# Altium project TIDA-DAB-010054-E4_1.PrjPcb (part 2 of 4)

## Sheet TIDA-DAB-010054-E4_SecondarySideSensing.SchDoc
size 431 x 279 mm; Date: Not shown in title block; ApprovedBy: Not shown in title block; CheckedBy: Not shown in title block; Author: Not shown in title block; CompanyName: Not shown in title block; Engineer: Not shown in title block; Organization: Not shown in title block; Address1: Not shown in title block; Address2: Not shown in title block; Address3: Not shown in title block; Address4: Not shown in title block; DocumentNumber: 1; Revision: Use project parameter SCH_Rev; SheetNumber: 4; SheetTotal: 11; PageSetup: Record=PageOptions¦CenterHorizontal=True¦CenterVertical=True¦PrintScale=1.00¦XCorrection=1.00¦YCorrection=1.00¦PrintKind=0¦BorderSize=5000000¦LeftOffset=0¦BottomOffset=0¦Orientation=2¦PaperLength=1000¦PaperWidth=1000¦Scale=100¦PaperSource=15¦PrintQuality=600¦MediaType=1¦DitherType=10¦PaperKind=Letter¦PrintScaleMode=1
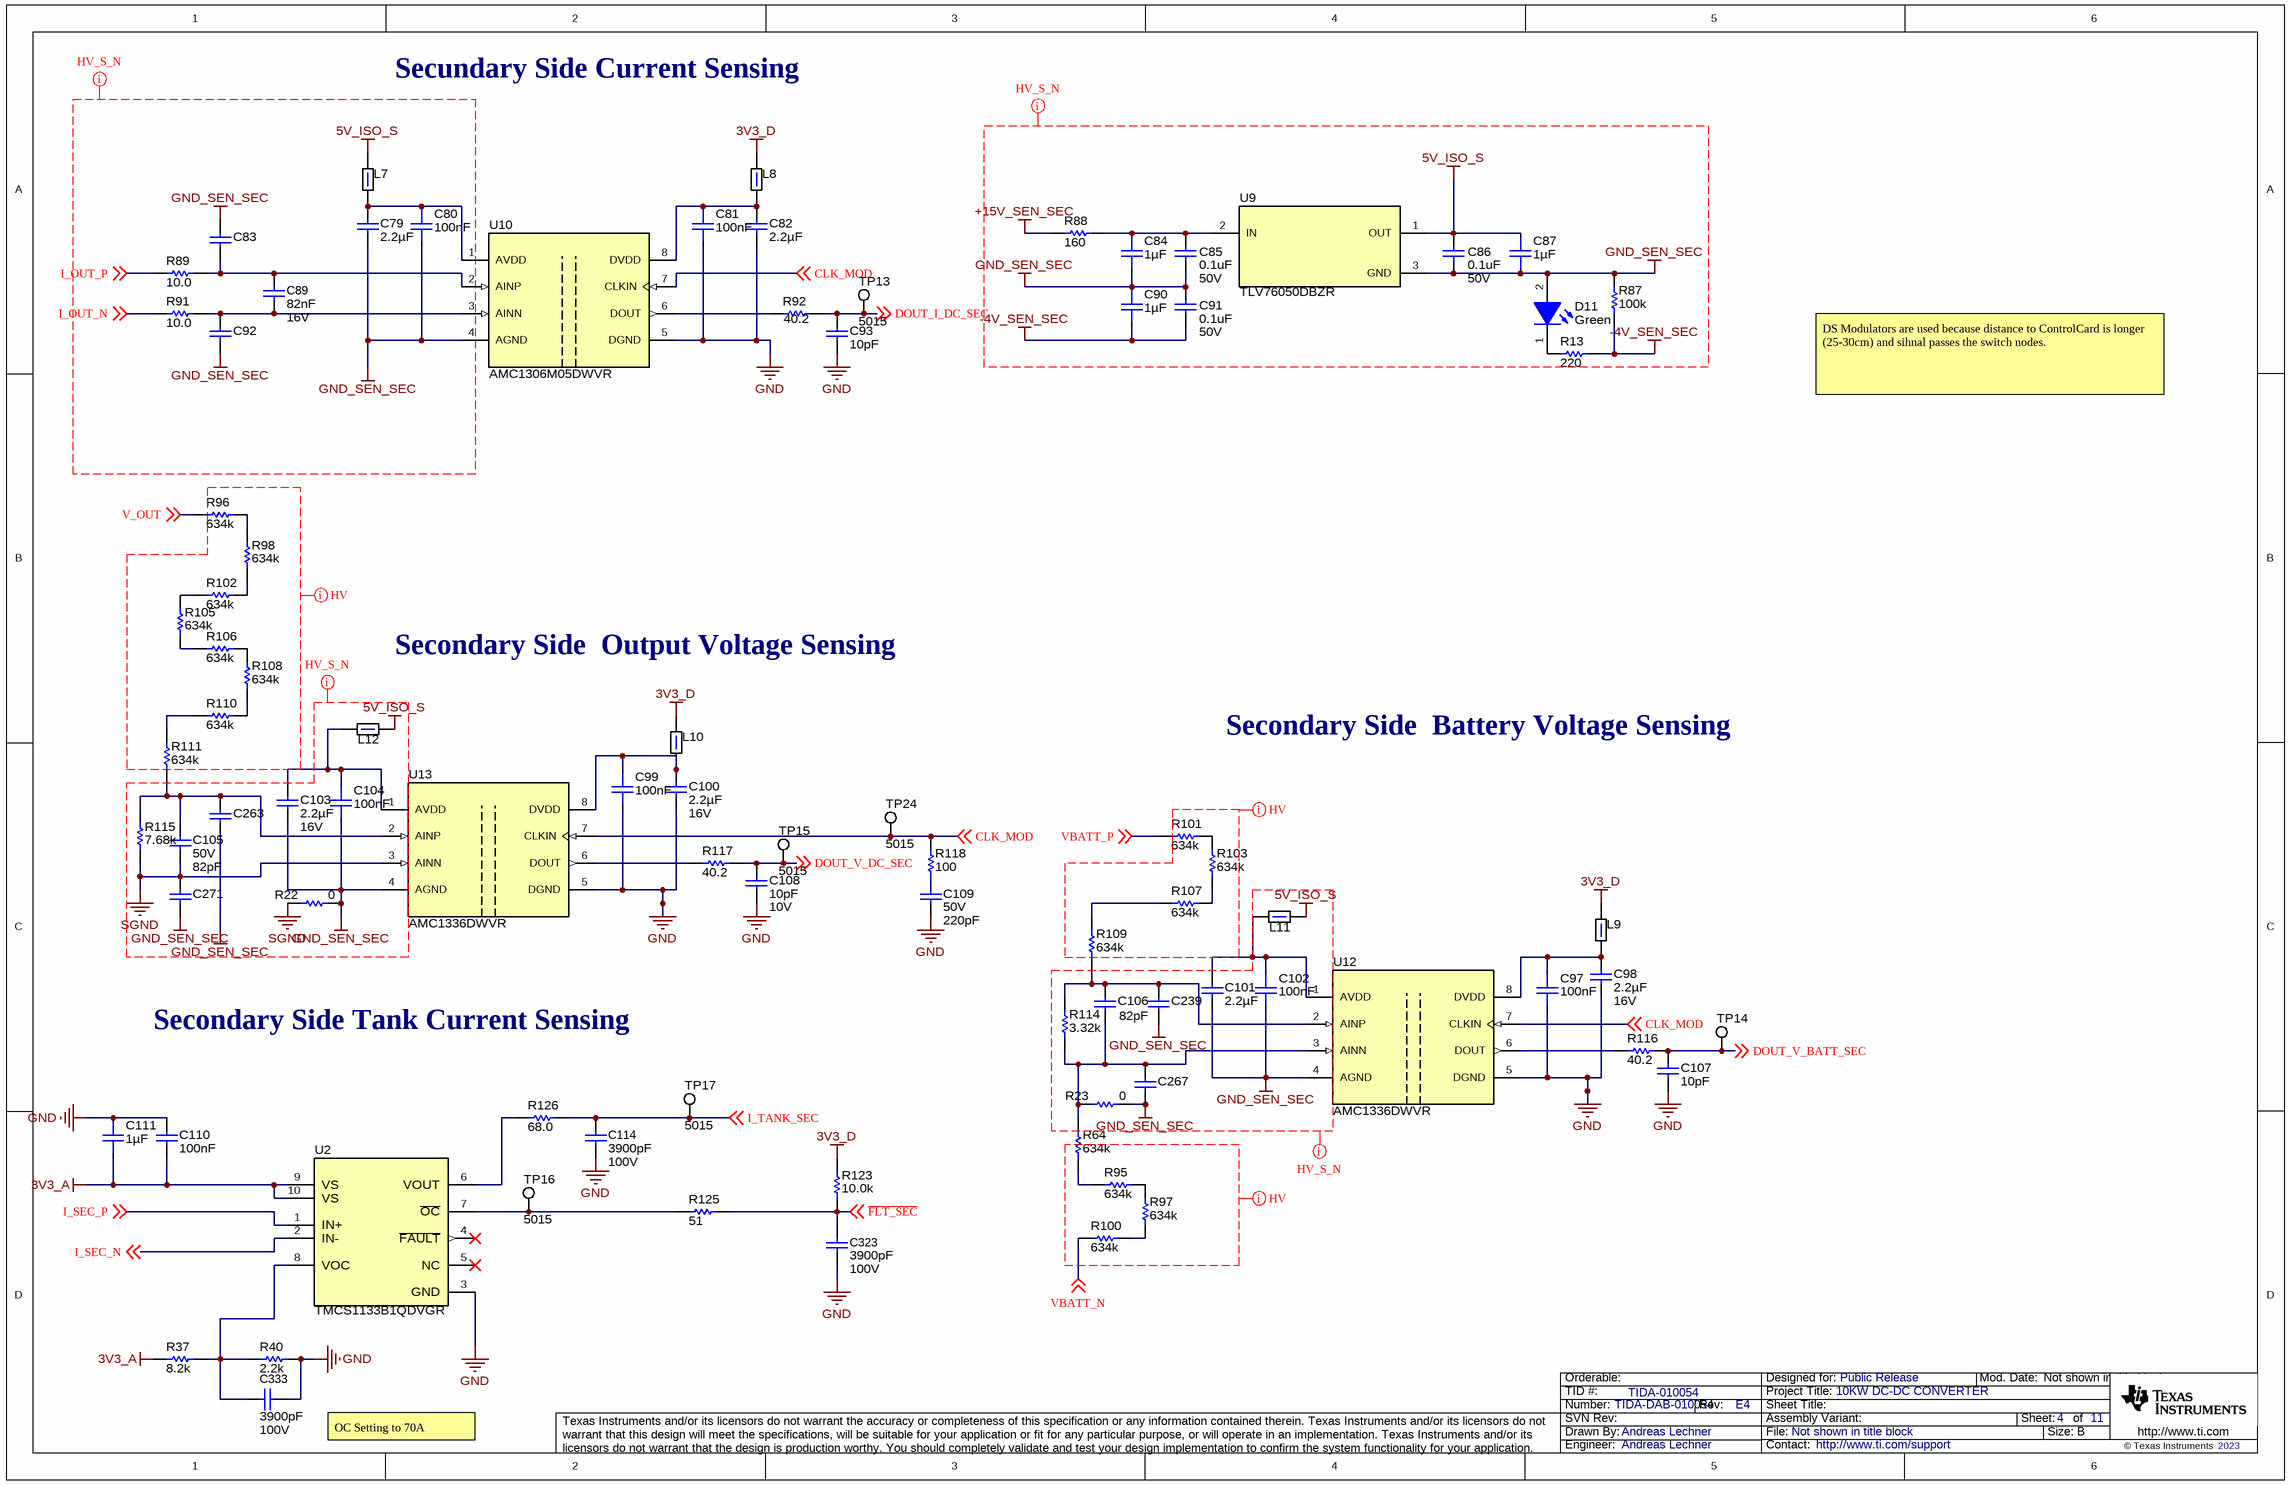
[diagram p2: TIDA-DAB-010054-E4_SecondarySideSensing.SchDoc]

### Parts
C79  Cap_F: 2.2µF  [0603]  (hidden comment: CC0603KRX7R7BB225)
C80  Cap_F: 100nF  [FP-CL10B104KA8VPJC_0603-MFG]  (hidden comment: CL10B104KA8VPJC)
C81  Cap_F: 100nF  [FP-CL10B104KA8VPJC_0603-MFG]  (hidden comment: CL10B104KA8VPJC)
C82  Cap_F: 2.2µF  [0603]  (hidden comment: CC0603KRX7R7BB225)
C83  0603ZC100KAT2A  [0603]  (value not drawn)
C84  Cap_F: 1µF  [FP-CL10B105KA8VPJC_0603-MFG]  (hidden comment: CL10B105KA8VPJC)
C85  VDC_V: 50V  ValueDisplayed: 0.1uF  [0402L]  (hidden comment: GCM155R71H104KE02D)
C86  VDC_V: 50V  ValueDisplayed: 0.1uF  [0402L]  (hidden comment: GCM155R71H104KE02D)
C87  Cap_F: 1µF  [FP-CL10B105KA8VPJC_0603-MFG]  (hidden comment: CL10B105KA8VPJC)
C89  Cap_F: 82nF  VDC_V: 16V  [0603]  (hidden comment: 0603YC823KAT2A)
C90  Cap_F: 1µF  [FP-CL10B105KA8VPJC_0603-MFG]  (hidden comment: CL10B105KA8VPJC)
C91  VDC_V: 50V  ValueDisplayed: 0.1uF  [0402L]  (hidden comment: GCM155R71H104KE02D)
C92  0603ZC100KAT2A  [0603]  (value not drawn)
C93  Cap_F: 10pF  [0603]  (hidden comment: 0603ZC100KAT2A)
C97  Cap_F: 100nF  [FP-CL10B104KA8VPJC_0603-MFG]  (hidden comment: CL10B104KA8VPJC)
C98  Cap_F: 2.2µF  VDC_V: 16V  [0603]  (hidden comment: CC0603KRX7R7BB225)
C99  Cap_F: 100nF  [FP-CL10B104KA8VPJC_0603-MFG]  (hidden comment: CL10B104KA8VPJC)
C100  Cap_F: 2.2µF  VDC_V: 16V  [0603]  (hidden comment: CC0603KRX7R7BB225)
C101  Cap_F: 2.2µF  [0603]  (hidden comment: CC0603KRX7R7BB225)
C102  Cap_F: 100nF  [FP-CL10B104KA8VPJC_0603-MFG]  (hidden comment: CL10B104KA8VPJC)
C103  Cap_F: 2.2µF  VDC_V: 16V  [0603]  (hidden comment: CC0603KRX7R7BB225)
C104  Cap_F: 100nF  [FP-CL10B104KA8VPJC_0603-MFG]  (hidden comment: CL10B104KA8VPJC)
C105  VDC_V: 50V  ValueDisplayed: 82pF  [0603]  (hidden comment: C0603C820K5GACTU)
C106  ValueDisplayed: 82pF  [0603]  (hidden comment: C0603C820K5GACTU)
C107  Cap_F: 10pF  [0603]  (hidden comment: 0603ZC100KAT2A)
C108  Cap_F: 10pF  VDC_V: 10V  [0603]  (hidden comment: 0603ZC100KAT2A)
C109  VDC_V: 50V  ValueDisplayed: 220pF  [0603]  (hidden comment: GRM1885C1H221JA01D)
C110  Cap_F: 100nF  [0603]  (hidden comment: 06033C104KAT2A)
C111  Cap_F: 1µF  [FP-CL10B105KA8VPJC_0603-MFG]  (hidden comment: CL10B105KA8VPJC)
C114  ValueDisplayed: 3900pF  VDC_V: 100V  [0603]  (hidden comment: C1608C0G2A392J080AE)
C239  0603ZC100KAT2A  [0603]  (value not drawn)
C263  0603ZC100KAT2A  [0603]  (value not drawn)
C267  0603ZC100KAT2A  [0603]  (value not drawn)
C271  0603ZC100KAT2A  [0603]  (value not drawn)
C323  ValueDisplayed: 3900pF  VDC_V: 100V  [0603]  (hidden comment: C1608C0G2A392J080AE)
C333  ValueDisplayed: 3900pF  VDC_V: 100V  [0603]  (hidden comment: C1608C0G2A392J080AE)
D11  value Green  [WL-SMCW_GREEN]  (hidden comment: 150060VS75000)
L7  74279228260  [0603]  (value not drawn)
L8  74279228260  [0603]  (value not drawn)
L9  74279228260  [0603]  (value not drawn)
L10  74279228260  [0603]  (value not drawn)
L11  74279228260  [0603]  (value not drawn)
L12  74279228260  [0603]  (value not drawn)
R13  ValueDisplayed: 220  [0603]  (hidden comment: CRCW0603220RJNEA)
R22  ValueDisplayed: 0  [0603]  (hidden comment: RMCF0603ZT0R00)
R23  ValueDisplayed: 0  [0603]  (hidden comment: RMCF0603ZT0R00)
R37  ValueDisplayed: 8.2k  [0603]  (hidden comment: RC0603JR-078K2L)
R40  ValueDisplayed: 2.2k  [0603]  (hidden comment: RC0603JR-072K2L)
R64  ValueDisplayed: 634k  [0805_HV1]  (hidden comment: RT0805BRD07634KL)
R87  ValueDisplayed: 100k  [0603]  (hidden comment: CRCW0603100KJNEAC)
R88  ValueDisplayed: 160  [1210]  (hidden comment: RC1210JR-07160RL)
R89  ValueDisplayed: 10.0  [0603]  (hidden comment: TNPW060310R0BEEA)
R91  ValueDisplayed: 10.0  [0603]  (hidden comment: TNPW060310R0BEEA)
R92  ValueDisplayed: 40.2  [0603]  (hidden comment: RC0603FR-0740R2L)
R95  ValueDisplayed: 634k  [0805_HV1]  (hidden comment: RT0805BRD07634KL)
R96  ValueDisplayed: 634k  [0805_HV1]  (hidden comment: RT0805BRD07634KL)
R97  ValueDisplayed: 634k  [0805_HV1]  (hidden comment: RT0805BRD07634KL)
R98  ValueDisplayed: 634k  [0805_HV1]  (hidden comment: RT0805BRD07634KL)
R100  ValueDisplayed: 634k  [0805_HV1]  (hidden comment: RT0805BRD07634KL)
R101  ValueDisplayed: 634k  [0805_HV1]  (hidden comment: RT0805BRD07634KL)
R102  ValueDisplayed: 634k  [0805_HV1]  (hidden comment: RT0805BRD07634KL)
R103  ValueDisplayed: 634k  [0805_HV1]  (hidden comment: RT0805BRD07634KL)
R105  ValueDisplayed: 634k  [0805_HV1]  (hidden comment: RT0805BRD07634KL)
R106  ValueDisplayed: 634k  [0805_HV1]  (hidden comment: RT0805BRD07634KL)
R107  ValueDisplayed: 634k  [0805_HV1]  (hidden comment: RT0805BRD07634KL)
R108  ValueDisplayed: 634k  [0805_HV1]  (hidden comment: RT0805BRD07634KL)
R109  ValueDisplayed: 634k  [0805_HV1]  (hidden comment: RT0805BRD07634KL)
R110  ValueDisplayed: 634k  [0805_HV1]  (hidden comment: RT0805BRD07634KL)
R111  ValueDisplayed: 634k  [0805_HV1]  (hidden comment: RT0805BRD07634KL)
R114  ValueDisplayed: 3.32k  [0603]  (hidden comment: RT0603BRD073K32L)
R115  ValueDisplayed: 7.68k  [0603]  (hidden comment: RT0603BRD077K68L)
R116  ValueDisplayed: 40.2  [0603]  (hidden comment: RC0603FR-0740R2L)
R117  ValueDisplayed: 40.2  [0603]  (hidden comment: RC0603FR-0740R2L)
R118  ValueDisplayed: 100  [0603]  (hidden comment: RC0603FR-07100RL)
R123  ValueDisplayed: 10.0k  [0603]  (hidden comment: CRCW06030000Z0EA)
R125  ValueDisplayed: 51  [0603]  (hidden comment: CRCW060351R0JNEA)
R126  ValueDisplayed: 68.0  [0603]  (hidden comment: RC0603FR-0768RL)
TP13  5015  [Testpoint_Keystone_Miniature]
TP14  5015  [Testpoint_Keystone_Miniature]  (value not drawn)
TP15  5015  [Testpoint_Keystone_Miniature]
TP16  5015  [Testpoint_Keystone_Miniature]
TP17  5015  [Testpoint_Keystone_Miniature]
TP24  5015  [Testpoint_Keystone_Miniature]
U2  TMCS1133B1QDVGR  [DVG0010A-MFG]
U9  TLV76050DBZR  [DBZ0003A_N]
U10  AMC1306M05DWVR  [DWV0008A]
U12  AMC1336DWVR  [DWV0008A]
U13  AMC1336DWVR  [DWV0008A]

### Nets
3V3_A: C110.1 C111.2 R37.1 U2.9(VS) U2.10(VS)
3V3_D: L8.2 L9.2 L10.2 R123.2
5V_ISO_S: C86.2 C87.1 L7.2 L11.2 L12.2 U9.1(OUT)
+15V_SEN_SEC: R88.1
-4V_SEN_SEC: C90.2 C91.1 R13.2 R87.1
GND: C81.2 C82.2 C93.2 C97.2 C98.2 C99.2 C100.2 C107.2 C108.2 C109.2 C110.2 C111.1 C114.2 C323.1 C333.2 R40.2 U2.3(GND) U10.5(DGND) U12.5(DGND) U13.5(DGND)
GND_SEN_SEC: C79.2 C80.2 C83.1 C84.2 C85.1 C86.1 C87.2 C90.1 C91.2 C92.2 C101.2 C102.2 C103.2 C104.2 C239.2 C263.2 C267.2 C271.2 D11.2(A) R22.2 R23.2 R87.2 U9.3(GND) U10.4(AGND) U12.4(AGND) U13.4(AGND)
SGND: C105.2 C271.1 R22.1 R115.1 U13.3(AINN)
~{FLT_SEC}: C323.2 R123.1 R125.2 ; off-sheet ~{FLT_SEC}
CLK_MOD: R118.2 TP24.1 U10.7(CLKIN) U12.7(CLKIN) U13.7(CLKIN) ; off-sheet CLK_MOD
DOUT_I_DC_SEC: C93.1 R92.2 TP13.1 ; off-sheet DOUT_I_DC_SEC
DOUT_V_BATT_SEC: C107.1 R116.2 TP14.1 ; off-sheet DOUT_V_BATT_SEC
DOUT_V_DC_SEC: C108.1 R117.2 TP15.1 ; off-sheet DOUT_V_DC_SEC
I_OUT_N: R91.1 ; off-sheet I_OUT_N
I_OUT_P: R89.1 ; off-sheet I_OUT_P
I_SEC_N: U2.2(IN-) ; off-sheet I_SEC_N  [project net D1L_S]
I_SEC_P: U2.1(IN+) ; off-sheet I_SEC_P
I_TANK_SEC: C114.1 R126.2 TP17.1 ; off-sheet I_TANK_SEC
V_OUT: R96.2 ; off-sheet V_OUT  [project net D1H_S]
VBATT_N: R100.1 ; off-sheet VBATT_N
VBATT_P: R101.2 ; off-sheet VBATT_P
NetC79_1: C79.1 C80.1 L7.1 U10.1(AVDD)
NetC81_1: C81.1 C82.1 L8.1 U10.8(DVDD)
NetC83_2: C83.2 C89.1 R89.2 U10.2(AINP)
NetC84_1: C84.1 C85.2 R88.2 U9.2(IN)
NetC89_2: C89.2 C92.1 R91.2 U10.3(AINN)
NetC97_1: C97.1 C98.1 L9.1 U12.8(DVDD)
NetC99_1: C99.1 C100.1 L10.1 U13.8(DVDD)
NetC101_1: C101.1 C102.1 L11.1 U12.1(AVDD)
NetC103_1: C103.1 C104.1 L12.1 U13.1(AVDD)
NetC105_1: C105.1 C263.1 R111.1 R115.2 U13.2(AINP)
NetC106_1: C106.1 C239.1 R109.1 R114.2 U12.2(AINP)
NetC106_2: C106.2 C267.1 R23.1 R64.2 R114.1 U12.3(AINN)
NetC109_1: C109.1 R118.1
NetC333_1: C333.1 R37.2 R40.1 U2.8(VOC)
NetD11_1: D11.1(K) R13.1
NetR64_1: R64.1 R95.1
NetR92_1: R92.1 U10.6(DOUT)
NetR95_2: R95.2 R97.1
NetR96_1: R96.1 R98.1
NetR97_2: R97.2 R100.2
NetR98_2: R98.2 R102.1
NetR101_1: R101.1 R103.2
NetR102_2: R102.2 R105.2
NetR103_1: R103.1 R107.1
NetR105_1: R105.1 R106.2
NetR106_1: R106.1 R108.2
NetR107_2: R107.2 R109.2
NetR108_1: R108.1 R110.1
NetR110_2: R110.2 R111.2
NetR116_1: R116.1 U12.6(DOUT)
NetR117_1: R117.1 U13.6(DOUT)
NetR125_1: R125.1 TP16.1 U2.7(~{OC})
NetR126_1: R126.1 U2.6(VOUT)

Not connected (* = marked no-connect by the designer): U2 4(~{FAULT})* 5(NC)*

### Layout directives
net class HV_S_N: 5V_ISO_S, +15V_SEN_SEC, -4V_SEN_SEC, GND_SEN_SEC, I_OUT_N, I_OUT_P, SGND
net class HV: (no net found under the mark), V_OUT, VBATT_P

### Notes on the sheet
- Secundary Side Current Sensing
- DS Modulators are used because distance to ControlCard is longer (25-30cm) and sihnal passes the switch nodes.
- Secondary Side  Output Voltage Sensing
- Secondary Side  Battery Voltage Sensing
- Secondary Side Tank Current Sensing
- OC Setting to 70A

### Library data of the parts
C79 C82 C101 = CMP-0079605-1: CAP, CERM, 2.2 µF, 16 V,+/- 10%, X7R, 0603; Manufacturer: Yageo America; TaMin_C: -55°C; Polarized: N; SizeAreaWB_mm2: 4.68; U/M: EA; Value: 2.2uF; TaMax_C: 125°C; SizeZ_mm: 1; SizeX_mm: 1.6; SizeY_mm: 0.8; Value2: 16V; SizeArea_mm2: 1.28; AEC Category: Q200
C80 C81 C97 C99 C102 C104 = CMP-0121051-1: Automotive CAP, 100㎋, 25V, ±10%, X7R, 0603, 5mm Bending; Manufacturer: Samsung; AEC Grade: Grade 1; AEC Qualified: Yes; SizeZ_mm: 0.9mm; TempCo: 15%; Value: 100nF
C83 C92 C93 C107 C239 C263 C267 C271 = CMP-0006811-4: CAP, CERM, 10 pF, 10 V, +/- 10%, X7R, 0603; Manufacturer: AVX; TaMin_C: -55°C; Polarized: N; SizeAreaWB_mm2: 4.68; Value1: Unknown; U/M: EA; Value: 10pF; TaMax_C: 125°C; SizeZ_mm: 1; SizeX_mm: 1.6; SizeY_mm: 0.8; Value2: 10V; SizeArea_mm2: 1.28; AEC Category: Q200
C84 C87 C90 C111 = CMP-0121052-1: Cap Ceramic 1uF 25V X7R ±10% Pad SMD 0603 +125°C T/R; Manufacturer: Samsung; AEC Grade: Grade 1; AEC Qualified: Yes; SizeZ_mm: 0.9mm; TempCo: 15%; Value: 1µF
C85 C86 C91 = CMP-0006356-2: CAP, CERM, 0.1 uF, 50 V, +/- 10%, X7R, AEC-Q200 Grade 1, 0402; Manufacturer: MuRata; TaMin_C: -55°C; Polarized: N; SizeAreaWB_mm2: 3; Value1: Unknown; U/M: EA; Value: 0.1uF; TaMax_C: 125°C; SizeZ_mm: 0.6; SizeX_mm: 1; SizeY_mm: 0.5; Cap_Case: 0402; AEC Qualified: Y; Cap_F: 100nF; AEC Category: Q200
C89 = CMP-0006810-4: CAP, CERM, 0.082 uF, 16 V, +/- 10%, X7R, 0603; Manufacturer: AVX; TaMin_C: -55°C; ESR_ohm: 42m; Polarized: N; SizeAreaWB_mm2: 4.68; Value1: 0.042 ohm; U/M: EA; TaMax_C: 125°C; SizeZ_mm: 1; SizeX_mm: 1.6; SizeY_mm: 0.8; SizeArea_mm2: 1.28; AEC Category: Q200
C98 C100 C103 = CMP-0079605-1: CAP, CERM, 2.2 µF, 16 V,+/- 10%, X7R, 0603; Manufacturer: Yageo America; TaMin_C: -55°C; Polarized: N; SizeAreaWB_mm2: 4.68; U/M: EA; Value: 2.2uF; TaMax_C: 125°C; SizeZ_mm: 1; SizeX_mm: 1.6; SizeY_mm: 0.8; SizeArea_mm2: 1.28; AEC Category: Q200
C105 = CMP-0006970-4: CAP, CERM, 82 pF, 50 V, +/- 10%, C0G/NP0, 0603; Manufacturer: Kemet; TaMin_C: -55°C; Polarized: N; SizeAreaWB_mm2: 4.68; Value1: Unknown; U/M: EA; Value: 82pF; TaMax_C: 125°C; SizeZ_mm: 1; SizeX_mm: 1.6; SizeY_mm: 0.8; SizeArea_mm2: 1.28; AEC Category: Q200
C106 = CMP-0006970-4: CAP, CERM, 82 pF, 50 V, +/- 10%, C0G/NP0, 0603; Manufacturer: Kemet; TaMin_C: -55°C; Polarized: N; SizeAreaWB_mm2: 4.68; Value1: Unknown; U/M: EA; Value: 82pF; TaMax_C: 125°C; SizeZ_mm: 1; SizeX_mm: 1.6; SizeY_mm: 0.8; Value2: 50V; SizeArea_mm2: 1.28; AEC Category: Q200
C108 = CMP-0006811-4: CAP, CERM, 10 pF, 10 V, +/- 10%, X7R, 0603; Manufacturer: AVX; TaMin_C: -55°C; Polarized: N; SizeAreaWB_mm2: 4.68; Value1: Unknown; U/M: EA; Value: 10pF; TaMax_C: 125°C; SizeZ_mm: 1; SizeX_mm: 1.6; SizeY_mm: 0.8; SizeArea_mm2: 1.28; AEC Category: Q200
C109 = CMP-0007197-4: CAP, CERM, 220 pF, 50 V, +/- 5%, C0G/NP0, 0603; Manufacturer: MuRata; TaMin_C: -55°C; Polarized: N; SizeAreaWB_mm2: 4.68; Value1: Unknown; U/M: EA; Value: 220pF; TaMax_C: 125°C; SizeZ_mm: 1; SizeX_mm: 1.6; SizeY_mm: 0.8; SizeArea_mm2: 1.28; AEC Category: Q200
C110 = CMP-0006753-4: CAP, CERM, 0.1 uF, 25 V, +/- 10%, X7R, 0603; Manufacturer: AVX; TaMin_C: -55°C; ESR_ohm: 0.05; Polarized: N; SizeAreaWB_mm2: 4.68; Value1: 0.05 ohm; U/M: EA; Value: 0.1uF; TaMax_C: 125°C; SizeZ_mm: 1; SizeX_mm: 1.6; SizeY_mm: 0.8; Value2: 25V; SizeArea_mm2: 1.28; AEC Category: Q200
C114 C323 C333 = CMP-0860987-1: CAP, CERM, 3900 pF, 100 V,+/- 5%, C0G/NP0, 0603; Manufacturer: TDK; SizeArea_mm2: 1.28; SizeY_mm: 0.8; AEC Qualified: N; Cap_F: 3.9nF; Value: 3900pF; U/M: EA; AEC Category: Q200; SizeZ_mm: 1; TaMin_C: -55°C; TaMax_C: 125°C; SizeAreaWB_mm2: 4.68; SizeX_mm: 1.6
D11 = CMP-0002894-2: LED, Green, SMD; Manufacturer: Wurth Elektronik; Type: AlInGaP; Value2: 2V; Io_A: 20mA; Value1: W
L7-L12 = CMP-0003155-2: Ferrite Bead, 26 ohm @ 100 MHz, 6.5 A, 0603; Manufacturer: Wurth Elektronik; Ztyp@1GHz_Ohm: 35.506; ZTyp@100MHz_Ohm: 26; SizeAreaWB_mm2: 4.68; DCR_ohm: 5m; Value1: 0.005 ohm; Value: 26 ohm; Imax_A: 6.5A; SizeZ_mm: 1; SizeX_mm: 1.6; SizeY_mm: 0.8; SizeArea_mm2: 1.28
R13 = CMP-0025756-4: RES, 220, 5%, 0.1 W, AEC-Q200 Grade 0, 0603; Manufacturer: Vishay-Dale; Power_W: 100mW; TempCo: 200 ppm/C; Value_Code: 220R; Value: 220; EIA_Code: E24; SizeX_mm: 1.6; SizeY_mm: 0.8; SizeZ_mm: 1; Value2: 0.1W; SizeArea_mm2: 1.28; AEC Qualified: Y; VDC_V: 75V; AEC Category: Q200; AEC Grade: 0
R22 R23 = CMP-0023343-3: RES, 0, 1%, 0.1 W, AEC-Q200 Grade 0, 0603; Manufacturer: Stackpole Electronics Inc; Power_W: 100mW; TempCo: ppm/C; U/M: EA; Value: 0; SizeX_mm: 1.6; SizeY_mm: 0.8; SizeZ_mm: 1; Value2: 0.1W; SizeArea_mm2: 1.28; CompType: Resistor; AEC Qualified: Y; AEC Category: Q200
R37 = CMP-0025942-5: RES, 8.2 k, 5%, 0.1 W, 0603; Manufacturer: Yageo; Power_W: 100mW; TempCo: 100 ppm/C; Value_Code: 8k20; Value: 8.2k; EIA_Code: E24; SizeX_mm: 1.6; SizeY_mm: 0.8; SizeZ_mm: 1; Value2: 0.1W; SizeArea_mm2: 1.28; AEC Qualified: N; VDC_V: 75V; AEC Category: Q200; SizeAreaWB_mm2: 4.68
R40 = CMP-0025906-5: RES, 2.2 k, 5%, 0.1 W, 0603; Manufacturer: Yageo; Power_W: 100mW; TempCo: 100 ppm/C; Value_Code: 2k20; Value: 2.2k; EIA_Code: E24; SizeX_mm: 1.6; SizeY_mm: 0.8; SizeZ_mm: 1; Value2: 0.1W; SizeArea_mm2: 1.28; VDC_V: 75V; SizeAreaWB_mm2: 4.68; AEC Qualified: N; AEC Category: Q200
R64 R95-R98 R100-R103 R105-R111 = CMP-0020237-2: RES, 634 k, 0.1%, 0.125 W, 0805; Manufacturer: Yageo America; Power_W: 125mW; TempCo: 25 ppm/C; U/M: EA; Value: 634k; EIA_Code: E192; SizeX_mm: 2; SizeY_mm: 1.25; SizeZ_mm: 1.45; Value2: 0.125W; SizeArea_mm2: 2.5; VDC_V: 150V; AEC Category: Q200
R87 = CMP-0082530-1: RES, 100 k, 5%, 0.1 W, 0603; Manufacturer: Vishay-Dale; Power_W: 100mW; TempCo: 200 ppm/C; SizeAreaWB_mm2: 4.68; Value: 100k; EIA_Code: E24; SizeX_mm: 1.6; SizeY_mm: 0.8; SizeZ_mm: 1; Value2: 0.1W; SizeArea_mm2: 1.28; AEC Qualified: N; VDC_V: 75V; AEC Category: Q200
R88 = CMP-0083464-1: RES, 160, 5%, 0.5 W, 1210; Manufacturer: Yageo; Power_W: 500mW; TempCo: 100 ppm/C; SizeAreaWB_mm2: 14.7; Value_Code: 160R; Value: 160; EIA_Code: E24; SizeX_mm: 3.2; SizeY_mm: 2.5; SizeZ_mm: 1.35; Value2: 0.5W; SizeArea_mm2: 8; AEC Qualified: N; VDC_V: 200V; AEC Category: Q200
R89 R91 = CMP-0025687-2: RES, 10.0, 0.1%, 0.1 W, 0603; Manufacturer: Vishay-Dale; Power_W: 100mW; TempCo: 25 ppm/C; Value_Code: 10R0; U/M: EA; Value: 10.0; EIA_Code: E192; Res_ohm: 10; SizeX_mm: 1.6; SizeY_mm: 0.8; SizeZ_mm: 1; Value2: 0.1W; SizeArea_mm2: 1.28; VDC_V: 75V; AEC Category: Q200
R92 R116 R117 = CMP-0023099-5: RES, 40.2, 1%, 0.1 W, 0603; Manufacturer: Yageo; Power_W: 100mW; TempCo: 100 ppm/C; Value_Code: 40R2; Value: 40.2; EIA_Code: E96; SizeX_mm: 1.6; SizeY_mm: 0.8; SizeZ_mm: 1; Value2: 0.1W; SizeArea_mm2: 1.28; AEC Qualified: N; VDC_V: 75V; AEC Category: Q200; SizeAreaWB_mm2: 4.68
R114 = CMP-0024194-2: RES, 3.32 k, 0.1%, 0.1 W, 0603; Manufacturer: Yageo America; Power_W: 100mW; TempCo: 25 ppm/C; Value_Code: 3k32; U/M: EA; Value: 3.32k; EIA_Code: E192; SizeX_mm: 1.6; SizeY_mm: 0.8; SizeZ_mm: 1; Value2: 0.1W; SizeArea_mm2: 1.28; VDC_V: 75V; AEC Category: Q200
R115 = CMP-0024483-2: RES, 7.68 k, 0.1%, 0.1 W, 0603; Manufacturer: Yageo America; Power_W: 100mW; TempCo: 25 ppm/C; Value_Code: 7k68; U/M: EA; Value: 7.68k; EIA_Code: E192; SizeX_mm: 1.6; SizeY_mm: 0.8; SizeZ_mm: 1; Value2: 0.1W; SizeArea_mm2: 1.28; VDC_V: 75V; AEC Category: Q200
R118 = CMP-0022736-4: RES, 100, 1%, 0.1 W, 0603; Manufacturer: Yageo; Power_W: 100mW; TempCo: 100 ppm/C; Value_Code: 100R; Value: 100; EIA_Code: E96; SizeX_mm: 1.6; SizeY_mm: 0.8; SizeZ_mm: 1; Value2: 0.1W; SizeArea_mm2: 1.28; AEC Qualified: N; VDC_V: 75V; AEC Category: Q200; SizeAreaWB_mm2: 4.68
R123 = CMP-0023337-3: RES, 10.0 k, 1%, 0.1 W, 0603; Manufacturer: Vishay Draloric; PartNumber: RCG060310K0FKEA; Power_W: 100mW; TempCo: 100 ppm/C; Value_Code: 10k0; U/M: EA; Value: 10.0k; EIA_Code: E96; Res_ohm: 10k; SizeX_mm: 1.6; SizeY_mm: 0.8; SizeZ_mm: 1; Value2: 0.1W; SizeArea_mm2: 1.28; AEC Qualified: N; VDC_V: 75V; AEC Category: Q200
R125 = CMP-0025825-4: RES, 51, 5%, 0.1 W, AEC-Q200 Grade 0, 0603; Manufacturer: Vishay-Dale; Power_W: 100mW; TempCo: 200 ppm/C; Value_Code: 51R0; Value: 51; EIA_Code: E24; SizeX_mm: 1.6; SizeY_mm: 0.8; SizeZ_mm: 1; Value2: 0.1W; SizeArea_mm2: 1.28; AEC Qualified: Y; VDC_V: 75V; AEC Category: Q200; AEC Grade: 0
R126 = CMP-0023241-5: RES, 68.0, 1%, 0.1 W, 0603; Manufacturer: Yageo; Power_W: 100mW; TempCo: 100 ppm/C; Value_Code: 68R0; Value: 68.0; Res_ohm: 68; SizeX_mm: 1.6; SizeY_mm: 0.8; SizeZ_mm: 1; Value2: 0.1W; SizeArea_mm2: 1.28; AEC Qualified: N; VDC_V: 75V; AEC Category: Q200; SizeAreaWB_mm2: 4.68
TP13-TP17 TP24 = CMP-0055152-2: Test Point, Miniature, SMT; Manufacturer: Keystone Electronics; CT: TRUE; Green_Lifecycle: Active; Green_REACh: Passed; CNHeader: FALSE
U2 = CMP-0097984-1: Manufacturer: Texas Instruments; Standoff Height: 0.1mm; SizeZ_mm: 2.65mm
U9 = CMP-0074892-1: 100-mA, 30-V, Fixed-Output, Linear-Voltage Regulator, DBZ0003A (SOT-23-3); Alternate PartNumber: TLV76050DBZT; Alternate Manufacturer: Texas Instruments; SizeAreaWB_mm2: 14.0; SizeZ_mm: 1.12; SizeX_mm: 2.5; SizeY_mm: 3.0; SizeArea_mm2: 7.5; CompType: IC; AEC Qualified: N; AEC Category: Q200
U10 = CMP-0013494-3: Small Reinforced Isolated Modulator With +/-50mV Input and CMOS Interface, DWV0008A (SOIC-8); Manufacturer: Texas Instruments; SizeArea_mm2: 67.275; CompType: IC; AEC Qualified: N; SizeX_mm: 11.5; SizeZ_mm: 2.8; SizeAreaWB_mm2: 105.975; AEC Category: Q200; Rating: Catalog; SizeY_mm: 5.85
U12 U13 = CMP-0860008-1: AMC1336 Small, High-Precision, Reinforced Isolated Delta-Sigma Modulator With Input Optimized for Voltage Sensing Applications, DWV0008A (SOIC-8); Manufacturer: Texas Instruments; AEC Qualified: N; AEC Category: Q200; SizeY_mm: 5.85; SizeX_mm: 11.5; SizeAreaWB_mm2: 105.975; SizeArea_mm2: 67.275; CompType: IC; SizeZ_mm: 2.8

## Sheet TIDA-DAB-010054-E4_GateDriverPrimHB1.SchDoc
size 431 x 279 mm; Date: Not shown in title block; ApprovedBy: Not shown in title block; CheckedBy: Not shown in title block; Author: Not shown in title block; CompanyName: Not shown in title block; Engineer: Not shown in title block; Organization: Not shown in title block; Address1: Not shown in title block; Address2: Not shown in title block; Address3: Not shown in title block; Address4: Not shown in title block; DocumentNumber: 1; Revision: Use project parameter SCH_Rev; SheetNumber: 5; SheetTotal: 11; PageSetup: Record=PageOptions¦CenterHorizontal=True¦CenterVertical=True¦PrintScale=1.00¦XCorrection=1.00¦YCorrection=1.00¦PrintKind=0¦BorderSize=5000000¦LeftOffset=0¦BottomOffset=0¦Orientation=2¦PaperLength=1000¦PaperWidth=1000¦Scale=100¦PaperSource=15¦PrintQuality=600¦MediaType=1¦DitherType=10¦PaperKind=Letter¦PrintScaleMode=1
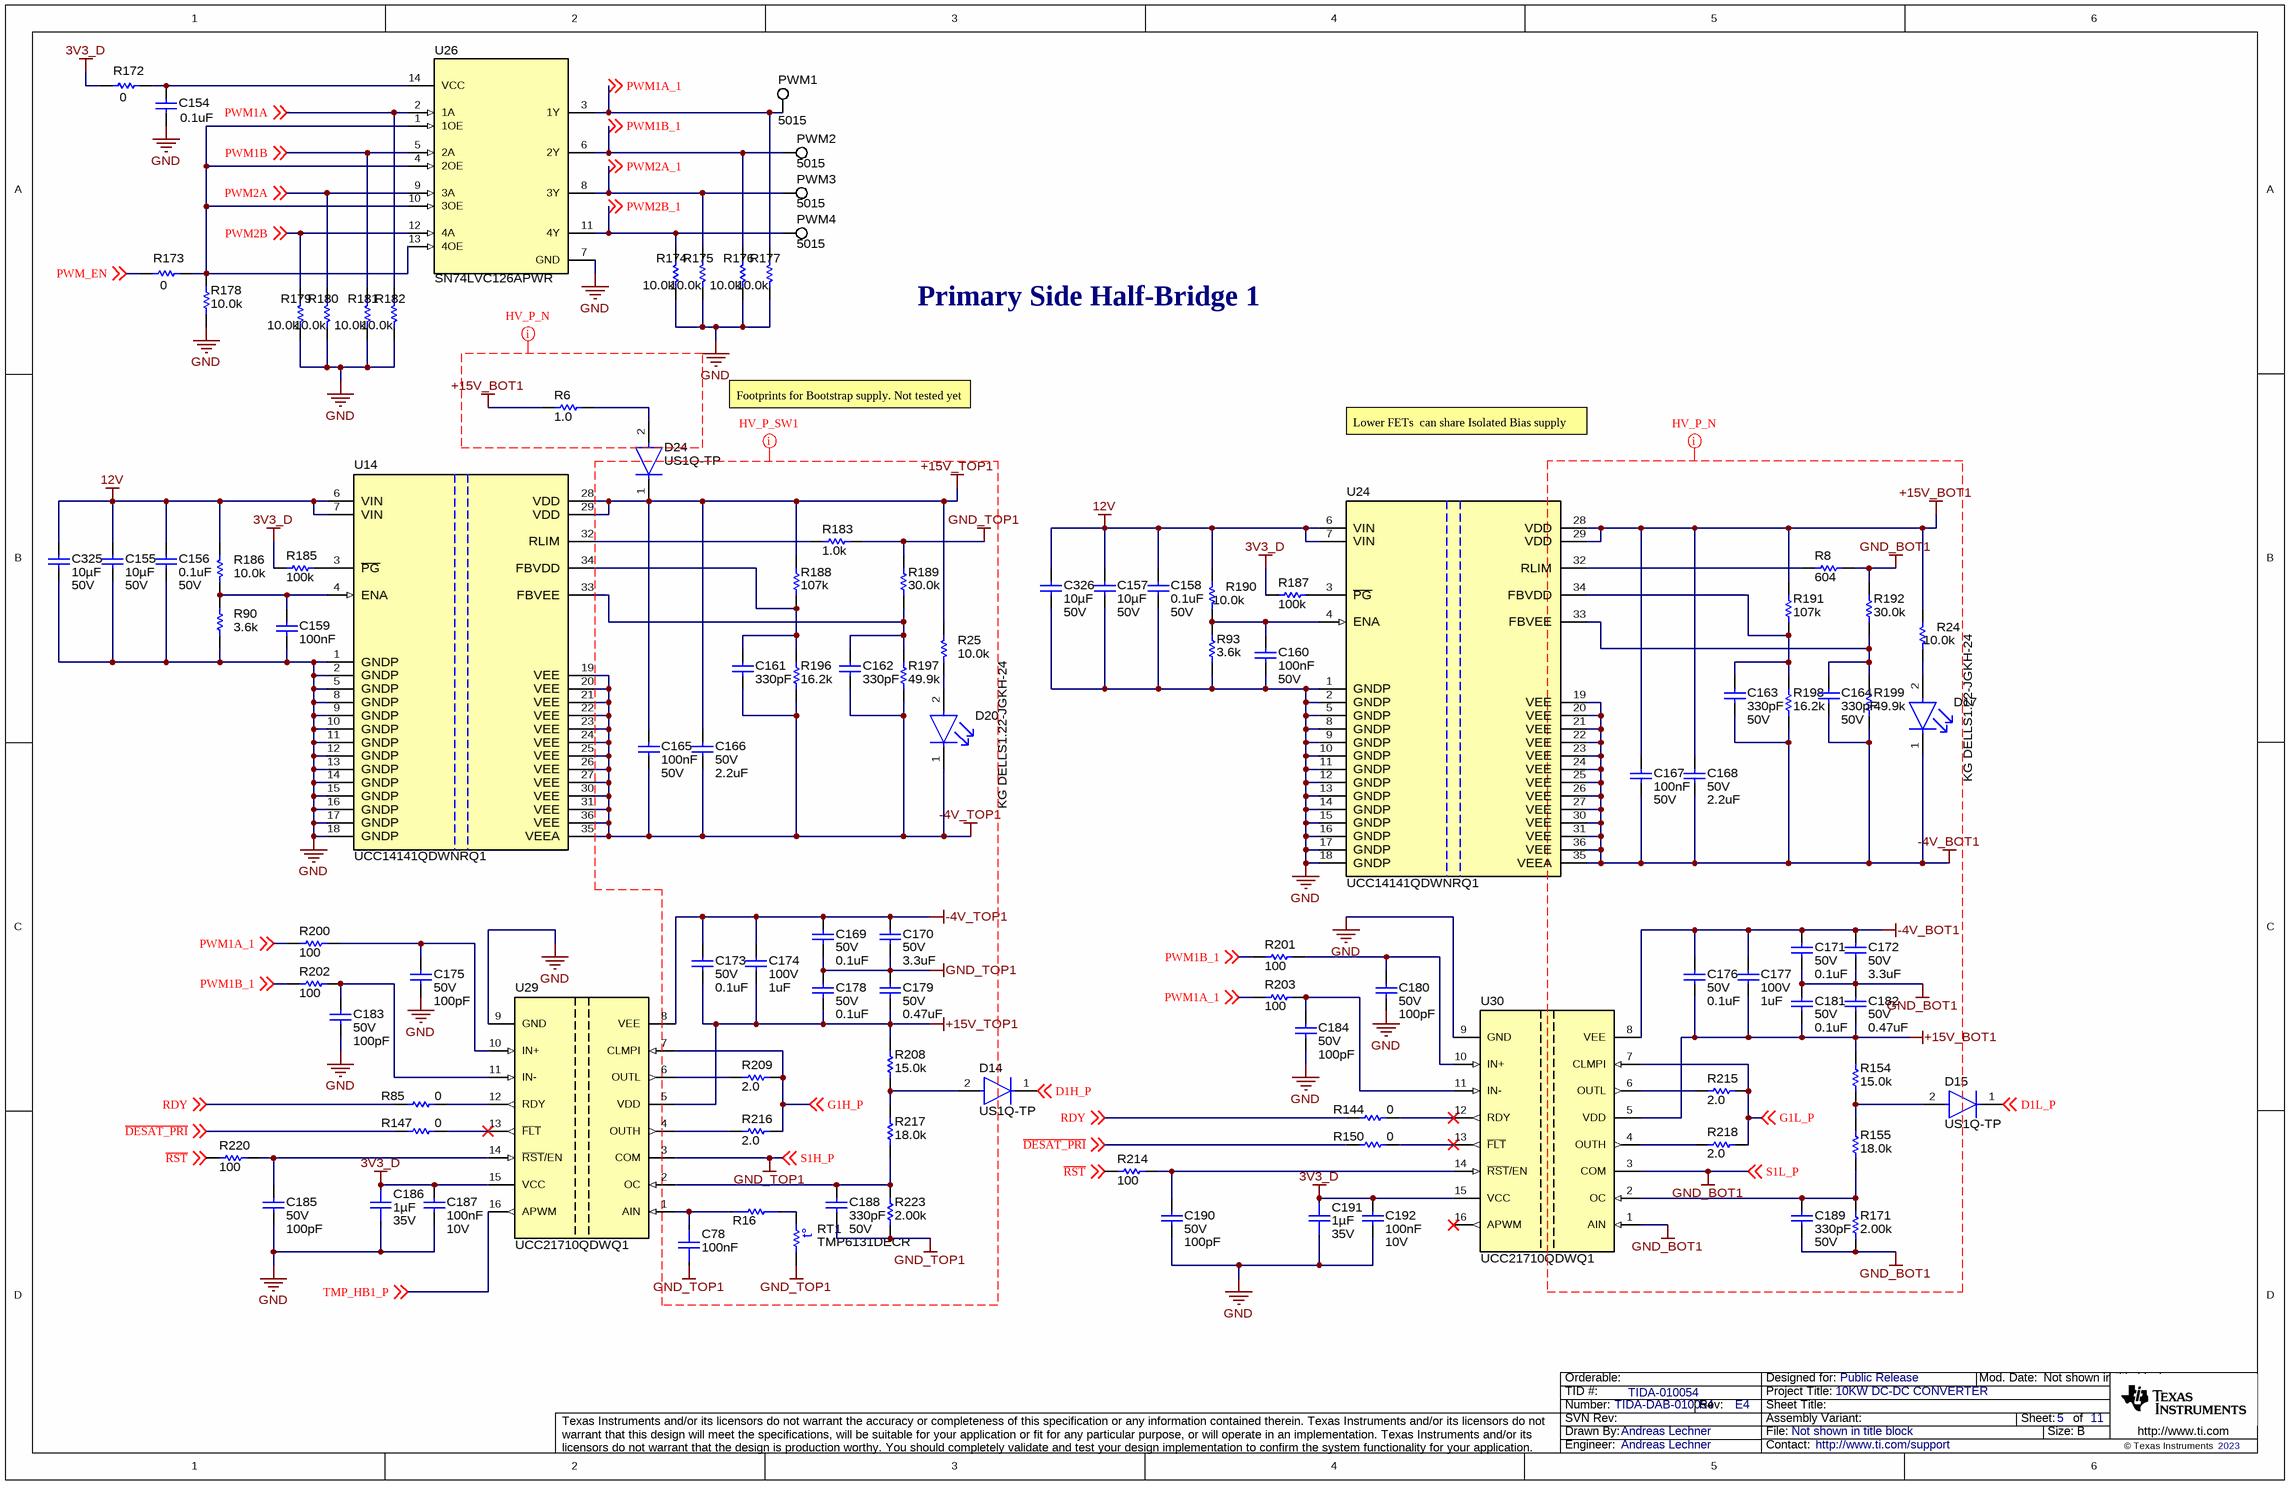
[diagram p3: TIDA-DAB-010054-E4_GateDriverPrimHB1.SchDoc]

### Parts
C78  Cap_F: 100nF  [FP-CL10B104KA8VPJC_0603-MFG]  (hidden comment: CL10B104KA8VPJC)
C154  ValueDisplayed: 0.1uF  [0603]  (hidden comment: 885012206095)
C155  ValueDisplayed: 10µF  VDC_V: 50V  [1206_190L]  (hidden comment: CGA5L1X7R1H106K160AC)
C156  value 0.1uF  VDC_V: 50V  [0603]  (hidden comment: CGA3E2X7R1H104K080AA)
C157  ValueDisplayed: 10µF  VDC_V: 50V  [1206_190L]  (hidden comment: CGA5L1X7R1H106K160AC)
C158  value 0.1uF  VDC_V: 50V  [0603]  (hidden comment: CGA3E2X7R1H104K080AA)
C159  Cap_F: 100nF  [0603]  (hidden comment: CGA3E2X7R1H104K080AA)
C160  Cap_F: 100nF  VDC_V: 50V  [0603]  (hidden comment: CGA3E2X7R1H104K080AA)
C161  Cap_F: 330pF  [0603]  (hidden comment: C0603C331K5RACTU)
C162  Cap_F: 330pF  [0603]  (hidden comment: C0603C331K5RACTU)
C163  Cap_F: 330pF  VDC_V: 50V  [0603]  (hidden comment: C0603C331K5RACTU)
C164  Cap_F: 330pF  VDC_V: 50V  [0603]  (hidden comment: C0603C331K5RACTU)
C165  Cap_F: 100nF  VDC_V: 50V  [0603]  (hidden comment: CGA3E2X7R1H104K080AA)
C166  VDC_V: 50V  ValueDisplayed: 2.2uF  [1206_180L]  (hidden comment: C3216X7R1H225K160AB)
C167  Cap_F: 100nF  VDC_V: 50V  [0603]  (hidden comment: CGA3E2X7R1H104K080AA)
C168  VDC_V: 50V  ValueDisplayed: 2.2uF  [1206_180L]  (hidden comment: C3216X7R1H225K160AB)
C169  VDC_V: 50V  ValueDisplayed: 0.1uF  [1206L]  (hidden comment: C1206C104K5RACTU)
C170  VDC_V: 50V  ValueDisplayed: 3.3uF  [1206_180L]  (hidden comment: C3216X5R1H335K160AB)
C171  VDC_V: 50V  ValueDisplayed: 0.1uF  [1206L]  (hidden comment: C1206C104K5RACTU)
C172  VDC_V: 50V  ValueDisplayed: 3.3uF  [1206_180L]  (hidden comment: C3216X5R1H335K160AB)
C173  VDC_V: 50V  ValueDisplayed: 0.1uF  [1206L]  (hidden comment: C1206C104K5RACTU)
C174  VDC_V: 100V  ValueDisplayed: 1uF  [1206_180L]  (hidden comment: C3216X7R2A105K160AA)
C175  VDC_V: 50V  ValueDisplayed: 100pF  [0603]  (hidden comment: C0603C101F5GACTU)
C176  VDC_V: 50V  ValueDisplayed: 0.1uF  [1206L]  (hidden comment: C1206C104K5RACTU)
C177  VDC_V: 100V  ValueDisplayed: 1uF  [1206_180L]  (hidden comment: C3216X7R2A105K160AA)
C178  VDC_V: 50V  ValueDisplayed: 0.1uF  [1206L]  (hidden comment: C1206C104K5RACTU)
C179  VDC_V: 50V  ValueDisplayed: 0.47uF  [1206_180L]  (hidden comment: C3216X7R1H474K160AA)
C180  VDC_V: 50V  ValueDisplayed: 100pF  [0603]  (hidden comment: C0603C101F5GACTU)
C181  VDC_V: 50V  ValueDisplayed: 0.1uF  [1206L]  (hidden comment: C1206C104K5RACTU)
C182  VDC_V: 50V  ValueDisplayed: 0.47uF  [1206_180L]  (hidden comment: C3216X7R1H474K160AA)
C183  VDC_V: 50V  ValueDisplayed: 100pF  [0603]  (hidden comment: C0603C101F5GACTU)
C184  VDC_V: 50V  ValueDisplayed: 100pF  [0603]  (hidden comment: C0603C101F5GACTU)
C185  VDC_V: 50V  ValueDisplayed: 100pF  [0603]  (hidden comment: C0603C101F5GACTU)
C186  Cap_F: 1µF  VDC_V: 35V  [FP-CL10B105KL9VPJC_0603-MFG]  (hidden comment: CL10B105KL9VPJC)
C187  Cap_F: 100nF  VDC_V: 10V  [0603]  (hidden comment: 0603ZC104KAT2A)
C188  Cap_F: 330pF  VDC_V: 50V  [0603]  (hidden comment: C0603C331K5RACTU)
C189  Cap_F: 330pF  VDC_V: 50V  [0603]  (hidden comment: C0603C331K5RACTU)
C190  VDC_V: 50V  ValueDisplayed: 100pF  [0603]  (hidden comment: C0603C101F5GACTU)
C191  Cap_F: 1µF  VDC_V: 35V  [FP-CL10B105KL9VPJC_0603-MFG]  (hidden comment: CL10B105KL9VPJC)
C192  Cap_F: 100nF  VDC_V: 10V  [0603]  (hidden comment: 0603ZC104KAT2A)
C325  ValueDisplayed: 10µF  VDC_V: 50V  [1206_190L]  (hidden comment: CGA5L1X7R1H106K160AC)
C326  ValueDisplayed: 10µF  VDC_V: 50V  [1206_190L]  (hidden comment: CGA5L1X7R1H106K160AC)
D14  US1Q-TP  [FP-US1Q-TP_SMA-MFG]
D15  US1Q-TP  [FP-US1Q-TP_SMA-MFG]
D17  KG DELLS1.22-JGKH-24  [FP-KG DELLS1.22-JGKH-24_0603-MFG]
D20  KG DELLS1.22-JGKH-24  [FP-KG DELLS1.22-JGKH-24_0603-MFG]
D24  US1Q-TP  [FP-US1Q-TP_SMA-MFG]
PWM1  5015  [Testpoint_Keystone_Miniature]
PWM2  5015  [Testpoint_Keystone_Miniature]
PWM3  5015  [Testpoint_Keystone_Miniature]
PWM4  5015  [Testpoint_Keystone_Miniature]
R6  ValueDisplayed: 1.0  [1206]  (hidden comment: CRM1206-JW-1R0ELF)
R8  ValueDisplayed: 604  [0805_HV]  (hidden comment: ERJ-P06F6040V)
R16  CH0603-10RJFTA  [FP-CH0603-10RJFTA_0603-MFG]  (value not drawn)
R24  ValueDisplayed: 10.0k  [0603]  (hidden comment: CRCW060310K0FKEA)
R25  ValueDisplayed: 10.0k  [0603]  (hidden comment: CRCW060310K0FKEA)
R85  ValueDisplayed: 0  [0603S]  (hidden comment: RMCF0603ZT0R00)
R90  ValueDisplayed: 3.6k  [0603]  (hidden comment: RC0603JR-073K6L)
R93  ValueDisplayed: 3.6k  [0603]  (hidden comment: RC0603JR-073K6L)
R144  ValueDisplayed: 0  [0603S]  (hidden comment: RMCF0603ZT0R00)
R147  ValueDisplayed: 0  [0603S]  (hidden comment: RMCF0603ZT0R00)
R150  ValueDisplayed: 0  [0603S]  (hidden comment: RMCF0603ZT0R00)
R154  ValueDisplayed: 15.0k  [0603]  (hidden comment: RC0603FR-0715KL)
R155  ValueDisplayed: 18.0k  [0603]  (hidden comment: ERJ3EKF1802V)
R171  ValueDisplayed: 2.00k  [0603]  (hidden comment: RC0603FR-072KL)
R172  ValueDisplayed: 0  [0603]  (hidden comment: ERJ-3GEY0R00V)
R173  ValueDisplayed: 0  [0603]  (hidden comment: ERJ-3GEY0R00V)
R174  ValueDisplayed: 10.0k  [0603]  (hidden comment: CRCW060310K0FKEA)
R175  ValueDisplayed: 10.0k  [0603]  (hidden comment: CRCW060310K0FKEA)
R176  ValueDisplayed: 10.0k  [0603]  (hidden comment: CRCW060310K0FKEA)
R177  ValueDisplayed: 10.0k  [0603]  (hidden comment: CRCW060310K0FKEA)
R178  ValueDisplayed: 10.0k  [0603]  (hidden comment: CRCW060310K0FKEA)
R179  ValueDisplayed: 10.0k  [0603]  (hidden comment: CRCW060310K0FKEA)
R180  ValueDisplayed: 10.0k  [0603]  (hidden comment: CRCW060310K0FKEA)
R181  ValueDisplayed: 10.0k  [0603]  (hidden comment: CRCW060310K0FKEA)
R182  ValueDisplayed: 10.0k  [0603]  (hidden comment: CRCW060310K0FKEA)
R183  ValueDisplayed: 1.0k  [0603]  (hidden comment: RCA06031K00JNEA)
R185  ValueDisplayed: 100k  [0603]  (hidden comment: CRCW0603100KJNEA)
R186  ValueDisplayed: 10.0k  [0603]  (hidden comment: CRCW060310K0FKEA)
R187  ValueDisplayed: 100k  [0603]  (hidden comment: CRCW0603100KJNEA)
R188  ValueDisplayed: 107k  [0603]  (hidden comment: RT0603BRD07107KL)
R189  ValueDisplayed: 30.0k  [0603]  (hidden comment: RG1608P-303-B-T5)
R190  ValueDisplayed: 10.0k  [0603]  (hidden comment: CRCW060310K0FKEA)
R191  ValueDisplayed: 107k  [0603]  (hidden comment: RT0603BRD07107KL)
R192  ValueDisplayed: 30.0k  [0603]  (hidden comment: RG1608P-303-B-T5)
R196  ValueDisplayed: 16.2k  [0603]  (hidden comment: RT0603BRD0716K2L)
R197  ValueDisplayed: 49.9k  [0603]  (hidden comment: RT0603BRD0749K9L)
R198  ValueDisplayed: 16.2k  [0603]  (hidden comment: RT0603BRD0716K2L)
R199  ValueDisplayed: 49.9k  [0603]  (hidden comment: RT0603BRD0749K9L)
R200  ValueDisplayed: 100  [0603]  (hidden comment: CRCW0603100RJNEA)
R201  ValueDisplayed: 100  [0603]  (hidden comment: CRCW0603100RJNEA)
R202  ValueDisplayed: 100  [0603]  (hidden comment: CRCW0603100RJNEA)
R203  ValueDisplayed: 100  [0603]  (hidden comment: CRCW0603100RJNEA)
R208  ValueDisplayed: 15.0k  [0603]  (hidden comment: RC0603FR-0715KL)
R209  ValueDisplayed: 2.0  [1206]  (hidden comment: CRCW12062R00JNEA)
R214  ValueDisplayed: 100  [0603]  (hidden comment: CRCW0603100RJNEA)
R215  ValueDisplayed: 2.0  [1206]  (hidden comment: CRCW12062R00JNEA)
R216  ValueDisplayed: 2.0  [1206]  (hidden comment: CRCW12062R00JNEA)
R217  ValueDisplayed: 18.0k  [0603]  (hidden comment: ERJ3EKF1802V)
R218  ValueDisplayed: 2.0  [1206]  (hidden comment: CRCW12062R00JNEA)
R220  ValueDisplayed: 100  [0603]  (hidden comment: CRCW0603100RJNEA)
R223  ValueDisplayed: 2.00k  [0603]  (hidden comment: RC0603FR-072KL)
RT1  TMP6131DECR  [DEC0002A]
U14  UCC14141QDWNRQ1  [DWJ0036A-MFG]
U24  UCC14141QDWNRQ1  [DWJ0036A-MFG]
U26  SN74LVC126APWR  [PW0014A_N]
U29  UCC21710QDWQ1  [DW0016B_HV]
U30  UCC21710QDWQ1  [DW0016B_HV]

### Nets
3V3_D: C186.2 C187.2 C191.2 C192.2 R172.1 R185.1 R187.1 U29.15(VCC) U30.15(VCC)
12V: C155.1 C156.1 C157.1 C158.1 C325.1 C326.1 R186.2 R190.2 U14.6(VIN) U14.7(VIN) U24.6(VIN) U24.7(VIN)
+15V_BOT1: C167.1 C168.1 C176.2 C177.2 C181.2 C182.2 R6.1 R24.2 R154.2 R191.2 U24.28(VDD) U24.29(VDD) U30.5(VDD)
+15V_TOP1: C165.1 C166.1 C173.2 C174.2 C178.2 C179.2 D24.1(CATHODE) R25.2 R188.2 R208.2 U14.28(VDD) U14.29(VDD) U29.5(VDD)
-4V_BOT1: C163.2 C164.2 C167.2 C168.2 C171.1 C172.1 C176.1 C177.1 D17.1(CATHODE) R198.1 R199.1 U24.19(VEE) U24.20(VEE) U24.21(VEE) U24.22(VEE) U24.23(VEE) U24.24(VEE) U24.25(VEE) U24.26(VEE) U24.27(VEE) U24.30(VEE) U24.31(VEE) U24.35(VEEA) U24.36(VEE) U30.8(VEE)
-4V_TOP1: C161.2 C162.2 C165.2 C166.2 C169.1 C170.1 C173.1 C174.1 D20.1(CATHODE) R196.1 R197.1 U14.19(VEE) U14.20(VEE) U14.21(VEE) U14.22(VEE) U14.23(VEE) U14.24(VEE) U14.25(VEE) U14.26(VEE) U14.27(VEE) U14.30(VEE) U14.31(VEE) U14.35(VEEA) U14.36(VEE) U29.8(VEE)
GND: C154.2 C155.2 C156.2 C157.2 C158.2 C159.2 C160.2 C175.2 C180.2 C183.2 C184.2 C185.2 C186.1 C187.1 C190.2 C191.1 C192.1 C325.2 C326.2 R90.1 R93.1 R174.1 R175.1 R176.1 R177.1 R178.1 R179.1 R180.1 R181.1 R182.1 U14.1(GNDP) U14.2(GNDP) U14.5(GNDP) U14.8(GNDP) U14.9(GNDP) U14.10(GNDP) U14.11(GNDP) U14.12(GNDP) U14.13(GNDP) U14.14(GNDP) U14.15(GNDP) U14.16(GNDP) U14.17(GNDP) U14.18(GNDP) U24.1(GNDP) U24.2(GNDP) U24.5(GNDP) U24.8(GNDP) U24.9(GNDP) U24.10(GNDP) U24.11(GNDP) U24.12(GNDP) U24.13(GNDP) U24.14(GNDP) U24.15(GNDP) U24.16(GNDP) U24.17(GNDP) U24.18(GNDP) U26.7(GND) U29.9(GND) U30.9(GND)
GND_BOT1: C171.2 C172.2 C181.1 C182.1 C189.2 R8.2 R171.1 R192.2 U30.1(AIN) U30.3(COM) ; off-sheet S1L_P  [also labelled S1L_P]
GND_TOP1: C78.1 C169.2 C170.2 C178.1 C179.1 C188.2 R183.2 R189.2 R223.1 RT1.1 U29.3(COM) ; off-sheet S1H_P  [also labelled S1H_P]
~{DESAT_PRI}: R147.1 R150.1 ; off-sheet ~{DESAT_PRI}
~{RST}: R214.1 R220.1 ; off-sheet ~{RST}
D1H_P: D14.1(CATHODE) ; off-sheet D1H_P
D1L_P: D15.1(CATHODE) ; off-sheet D1L_P
G1H_P: R209.2 R216.2 U29.7(CLMPI) ; off-sheet G1H_P
G1L_P: R215.2 R218.2 U30.7(CLMPI) ; off-sheet G1L_P
PWM1A: R182.2 U26.2(1A) ; off-sheet PWM1A
PWM1A_1: PWM1.1 R177.2 R200.1 R203.1 U26.3(1Y) ; off-sheet PWM1A_1
PWM1B: R181.2 U26.5(2A) ; off-sheet PWM1B
PWM1B_1: PWM2.1 R176.2 R201.1 R202.1 U26.6(2Y) ; off-sheet PWM1B_1
PWM2A: R180.2 U26.9(3A) ; off-sheet PWM2A
PWM2A_1: PWM3.1 R175.2 U26.8(3Y) ; off-sheet PWM2A_1
PWM2B: R179.2 U26.12(4A) ; off-sheet PWM2B
PWM2B_1: PWM4.1 R174.2 U26.11(4Y) ; off-sheet PWM2B_1
PWM_EN: R173.1 ; off-sheet PWM_EN
RDY: R85.1 R144.1 ; off-sheet RDY
TMP_HB1_P: U29.16(APWM) ; off-sheet TMP_HB1_P
NetC78_2: C78.2 R16.1 U29.1(AIN)
NetC154_1: C154.1 R172.2 U26.14(VCC)
NetC159_1: C159.1 R90.2 R186.1 U14.4(ENA)
NetC160_1: C160.1 R93.2 R190.1 U24.4(ENA)
NetC161_1: C161.1 R188.1 R196.2 U14.34(FBVDD)
NetC162_1: C162.1 R189.1 R197.2 U14.33(FBVEE)
NetC163_1: C163.1 R191.1 R198.2 U24.34(FBVDD)
NetC164_1: C164.1 R192.1 R199.2 U24.33(FBVEE)
NetC175_1: C175.1 R200.2 U29.10(IN+)
NetC180_1: C180.1 R201.2 U30.10(IN+)
NetC183_1: C183.1 R202.2 U29.11(IN-)
NetC184_1: C184.1 R203.2 U30.11(IN-)
NetC185_1: C185.1 R220.2 U29.14(~{RST}/EN)
NetC188_1: C188.1 R217.1 R223.2 U29.2(OC)
NetC189_1: C189.1 R155.1 R171.2 U30.2(OC)
NetC190_1: C190.1 R214.2 U30.14(~{RST}/EN)
NetD14_2: D14.2(ANODE) R208.1 R217.2
NetD15_2: D15.2(ANODE) R154.1 R155.2
NetD17_2: D17.2(ANODE) R24.1
NetD20_2: D20.2(ANODE) R25.1
NetD24_2: D24.2(ANODE) R6.2
NetR8_1: R8.1 U24.32(RLIM)
NetR16_2: R16.2 RT1.2
NetR85_2: R85.2 U29.12(RDY)
NetR144_2: R144.2 U30.12(RDY)
NetR147_2: R147.2 U29.13(~{FLT})
NetR150_2: R150.2 U30.13(~{FLT})
NetR173_2: R173.2 R178.2 U26.1(1OE) U26.4(2OE) U26.10(3OE) U26.13(4OE)
NetR183_1: R183.1 U14.32(RLIM)
NetR185_2: R185.2 U14.3(~{PG})
NetR187_2: R187.2 U24.3(~{PG})
NetR209_1: R209.1 U29.6(OUTL)
NetR215_1: R215.1 U30.6(OUTL)
NetR216_1: R216.1 U29.4(OUTH)
NetR218_1: R218.1 U30.4(OUTH)

Not connected (* = marked no-connect by the designer): U30 16(APWM)*

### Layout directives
net class HV_P_SW1: +15V_TOP1, -4V_TOP1, G1H_P, GND_TOP1, S1H_P
net class HV_P_N: +15V_BOT1, -4V_BOT1, G1L_P, GND_BOT1, S1L_P

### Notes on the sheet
- Primary Side Half-Bridge 1
- Footprints for Bootstrap supply. Not tested yet
- Lower FETs  can share Isolated Bias supply

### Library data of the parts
C78 = CMP-0121051-1: as C80 on sheet TIDA-DAB-010054-E4_SecondarySideSensing
C154 = CMP-0006837-4: CAP, CERM, 0.1 uF, 50 V, +/- 10%, X7R, 0603; Manufacturer: Wurth Elektronik; TaMin_C: -55°C; Polarized: N; SizeAreaWB_mm2: 4.68; Value1: Unknown; U/M: EA; Value: 0.1uF; TaMax_C: 125°C; SizeZ_mm: 1; SizeX_mm: 1.6; SizeY_mm: 0.8; Value2: 50V; SizeArea_mm2: 1.28; CompType: Capacitor; Cap_F: 100nF; AEC Category: Q200
C155 C157 C325 C326 = CMP-0085950-1: CAP, CERM, 10 µF, 50 V,+/- 10%, X7R, AEC-Q200 Grade 1, 1206; Manufacturer: TDK; SizeZ_mm: 1.9; Value: 10uF; Cap_Case: 1206; AEC Grade: 1; TaMin_C: -55°C; U/M: EA; SizeArea_mm2: 5.12; TaMax_C: 125°C; AEC Qualified: Y; AEC Category: Q200; SizeX_mm: 3.2; SizeY_mm: 1.6; Polarized: N; SizeAreaWB_mm2: 10.92
C156 C158 = CMP-0007078-4: CAP, CERM, 0.1 uF, 50 V, +/- 10%, X7R, AEC-Q200 Grade 1, 0603; Manufacturer: TDK; TaMin_C: -55°C; ESR_ohm: 29.6m; Polarized: N; SizeAreaWB_mm2: 4.68; Value1: 0.0296 ohm; U/M: EA; TaMax_C: 125°C; SizeZ_mm: 1; SizeX_mm: 1.6; SizeY_mm: 0.8; SizeArea_mm2: 1.28; AEC Qualified: Y; Cap_F: 100nF; IRMS_A: 971.99mA; AEC Category: Q200
C159 = CMP-0007078-4: CAP, CERM, 0.1 uF, 50 V, +/- 10%, X7R, AEC-Q200 Grade 1, 0603; Manufacturer: TDK; TaMin_C: -55°C; ESR_ohm: 29.6m; Polarized: N; SizeAreaWB_mm2: 4.68; Value1: 0.0296 ohm; U/M: EA; Value: 0.1uF; TaMax_C: 125°C; SizeZ_mm: 1; SizeX_mm: 1.6; SizeY_mm: 0.8; Value2: 50V; SizeArea_mm2: 1.28; AEC Qualified: Y; IRMS_A: 971.99mA; AEC Category: Q200
C160 C165 C167 = CMP-0007078-4: CAP, CERM, 0.1 uF, 50 V, +/- 10%, X7R, AEC-Q200 Grade 1, 0603; Manufacturer: TDK; TaMin_C: -55°C; ESR_ohm: 29.6m; Polarized: N; SizeAreaWB_mm2: 4.68; Value1: 0.0296 ohm; U/M: EA; Value: 0.1uF; TaMax_C: 125°C; SizeZ_mm: 1; SizeX_mm: 1.6; SizeY_mm: 0.8; SizeArea_mm2: 1.28; AEC Qualified: Y; IRMS_A: 971.99mA; AEC Category: Q200
C161 C162 = CMP-0006921-4: CAP, CERM, 330 pF, 50 V, +/- 10%, X7R, 0603; Manufacturer: Kemet; TaMin_C: -55°C; Polarized: N; SizeAreaWB_mm2: 4.68; Value1: Unknown; U/M: EA; Value: 330pF; TaMax_C: 125°C; SizeZ_mm: 1; SizeX_mm: 1.6; SizeY_mm: 0.8; Value2: 50V; SizeArea_mm2: 1.28; AEC Category: Q200
C163 C164 C188 C189 = CMP-0006921-4: CAP, CERM, 330 pF, 50 V, +/- 10%, X7R, 0603; Manufacturer: Kemet; TaMin_C: -55°C; Polarized: N; SizeAreaWB_mm2: 4.68; Value1: Unknown; U/M: EA; Value: 330pF; TaMax_C: 125°C; SizeZ_mm: 1; SizeX_mm: 1.6; SizeY_mm: 0.8; SizeArea_mm2: 1.28; AEC Category: Q200
C166 C168 = CMP-0008698-2: CAP, CERM, 2.2 uF, 50 V, +/- 10%, X7R, 1206; Manufacturer: TDK; TaMin_C: -55°C; ESR_ohm: 5.887m; Polarized: N; SizeAreaWB_mm2: 10.92; Value1: 0.005887 ohm; U/M: EA; Value: 2.2uF; TaMax_C: 125°C; SizeZ_mm: 1.8; SizeX_mm: 3.2; SizeY_mm: 1.6; Cap_Case: 1206_180; SizeArea_mm2: 5.12; Cap_F: 2.2µF; IRMS_A: 2.9923A; AEC Category: Q200
C169 C171 C173 C176 C178 C181 = CMP-0008586-2: CAP, CERM, 0.1 uF, 50 V, +/- 10%, X7R, 1206; Manufacturer: Kemet; TaMin_C: -55°C; ESR_ohm: 59m; Polarized: N; SizeAreaWB_mm2: 10.92; Value1: 0.059 ohm; U/M: EA; Value: 0.1uF; TaMax_C: 125°C; SizeZ_mm: 1.35; SizeX_mm: 3.2; SizeY_mm: 1.6; Cap_Case: 1206; SizeArea_mm2: 5.12; Cap_F: 100nF; IRMS_A: 1.2A; AEC Category: Q200
C170 C172 = CMP-0008661-2: CAP, CERM, 3.3 uF, 50 V, +/- 10%, X5R, 1206; Manufacturer: TDK; TaMin_C: -55°C; ESR_ohm: 4.773m; Polarized: N; SizeAreaWB_mm2: 10.92; Value1: 0.004773 ohm; U/M: EA; Value: 3.3uF; TaMax_C: 85°C; SizeZ_mm: 1.8; SizeX_mm: 3.2; SizeY_mm: 1.6; Cap_Case: 1206_180; SizeArea_mm2: 5.12; Cap_F: 3.3µF; IRMS_A: 3.3221A; AEC Category: Q200
C174 C177 = CMP-0008710-2: CAP, CERM, 1 uF, 100 V, +/- 10%, X7R, 1206; Manufacturer: TDK; TaMin_C: -55°C; ESR_ohm: 4.575m; Polarized: N; SizeAreaWB_mm2: 10.92; Value1: 0.004575 ohm; U/M: EA; Value: 1uF; TaMax_C: 125°C; SizeZ_mm: 1.8; SizeX_mm: 3.2; SizeY_mm: 1.6; Cap_Case: 1206_180; SizeArea_mm2: 5.12; Cap_F: 1µF; IRMS_A: 3.3964A; AEC Category: Q200
C175 C180 C183-C185 C190 = CMP-0080091-1: CAP, CERM, 100 pF, 50 V,+/- 1%, C0G/NP0, 0603; Manufacturer: Kemet; SizeAreaWB_mm2: 4.68; SizeArea_mm2: 1.28; AEC Qualified: N; AEC Category: Q200; Value: 100pF; TaMax_C: 125°C; SizeZ_mm: 1; Green_REACh: Passed; TaMin_C: -55°C; SizeY_mm: 0.8; Green_Lifecycle: Active; U/M: EA; SizeX_mm: 1.6
C179 C182 = CMP-0008701-2: CAP, CERM, 0.47 uF, 50 V, +/- 10%, X7R, 1206; Manufacturer: TDK; TaMin_C: -55°C; ESR_ohm: 9.426m; Polarized: N; SizeAreaWB_mm2: 10.92; Value1: 0.009426 ohm; U/M: EA; Value: 0.47uF; TaMax_C: 125°C; SizeZ_mm: 1.8; SizeX_mm: 3.2; SizeY_mm: 1.6; Cap_Case: 1206_180; SizeArea_mm2: 5.12; Cap_F: 470nF; IRMS_A: 2.3705A; AEC Category: Q200
C186 C191 = CMP-0121053-1: Automotive CAP, 1㎌, 35V, ±10%, X7R, 0603, 5mm Bending; Manufacturer: Samsung; AEC Grade: Grade 1; AEC Qualified: Yes; SizeZ_mm: 1mm; TempCo: 15%; ValueDisplayed: 1uF; Value: 1µF
C187 C192 = CMP-0006815-4: CAP, CERM, 0.1 uF, 10 V, +/- 10%, X7R, 0603; Manufacturer: AVX; TaMin_C: -55°C; Polarized: N; SizeAreaWB_mm2: 4.68; Value1: Unknown; U/M: EA; Value: 0.1uF; TaMax_C: 125°C; SizeZ_mm: 1; SizeX_mm: 1.6; SizeY_mm: 0.8; SizeArea_mm2: 1.28; AEC Category: Q200
D14 D15 D24 = CMP-0095286-1: Diode Standard 1200 V 1A Surface Mount DO-214AC (SMA); Manufacturer: MCC; Cap_F: 45pF; Max Surge Forward Current: 30A; SizeZ_mm: 2.44mm; TJmax_C: 150°C; Vr_V: 1.2kV; Peak Reverse Current: 5uA; AEC Qualified: No
D17 D20 = CMP-0093310-1: Standard LEDs - SMD Green TOPLED E 1608; Manufacturer: Osram Opto; AEC Grade: Grade 2; LambdaP: 572nm; SizeZ_mm: 0.7mm; LuminousFlux_PhiV: 0.016-0.0295lm; Luminous Intensity: 4.5-9.7mcd; LambdaD: 570nm; Tjmax_C: 125°C; Angle: 120°; Led Orientation: Top View; Forward Current: 2mA; Vf_V: 1.8V; AEC Qualified: Yes; Vr_V: 12V
PWM1-PWM4 = CMP-0055152-2: as TP13-TP17 on sheet TIDA-DAB-010054-E4_SecondarySideSensing
R6 = CMP-0018745-2: RES, 1.0, 5%, 0.5 W, 1206; Manufacturer: Bourns; Power_W: 500mW; TempCo: 150 ppm/C; Value_Code: 1R00; U/M: EA; Value: 1.0; EIA_Code: E24; Res_ohm: 1; SizeX_mm: 3.2; SizeY_mm: 1.6; SizeZ_mm: 1.35; Value2: 0.5W; SizeArea_mm2: 5.12; VDC_V: 1V; AEC Category: Q200
R8 = CMP-0021853-2: RES, 604, 1%, 0.5 W, 0805; Manufacturer: Panasonic; Power_W: 500mW; TempCo: 100 ppm/C; Value_Code: 604R; U/M: EA; Value: 604; EIA_Code: E96; SizeX_mm: 2; SizeY_mm: 1.25; SizeZ_mm: 1.45; Value2: 0.5W; SizeArea_mm2: 2.5; AEC Qualified: N; VDC_V: 400V; AEC Category: Q200
R16 = CMP-0091849-1: Res Thin Film 0603 10Ohm 5% 1/8W ±100ppm/°C Molded T/R; Manufacturer: Vishay; SizeZ_mm: 0.627mm; Power_W: 125mW; AEC Qualified: No; Value: 10; VDC_V: 50V
R24 R25 R174-R182 R186 R190 = CMP-0021998-4: RES, 10.0 k, 1%, 0.1 W, AEC-Q200 Grade 0, 0603; Manufacturer: Vishay-Dale; Value: 10.0k; Res_ohm: 10k; Value_Code: 10k0; Power_W: 100mW; Value2: 0.1W; VDC_V: 75V; TempCo: 100 ppm/C; SizeArea_mm2: 1.28; SizeX_mm: 1.6; SizeY_mm: 0.8; SizeZ_mm: 1; EIA_Code: E96; AEC Category: Q200; AEC Qualified: Y; AEC Grade: 0
R85 R144 R147 R150 = CMP-0023343-3: as R22 on sheet TIDA-DAB-010054-E4_SecondarySideSensing
R90 R93 = CMP-0025919-5: RES, 3.6 k, 5%, 0.1 W, 0603; Manufacturer: Yageo; Power_W: 100mW; TempCo: 100 ppm/C; Value_Code: 3k60; Value: 3.6k; EIA_Code: E24; SizeX_mm: 1.6; SizeY_mm: 0.8; SizeZ_mm: 1; Value2: 0.1W; SizeArea_mm2: 1.28; AEC Qualified: N; VDC_V: 75V; AEC Category: Q200; SizeAreaWB_mm2: 4.68
R154 R208 = CMP-0022816-5: RES, 15.0 k, 1%, 0.1 W, 0603; Manufacturer: Yageo; Power_W: 100mW; TempCo: 100 ppm/C; Value_Code: 15k0; Value: 15.0k; EIA_Code: E96; Res_ohm: 15k; SizeX_mm: 1.6; SizeY_mm: 0.8; SizeZ_mm: 1; Value2: 0.1W; SizeArea_mm2: 1.28; AEC Qualified: N; VDC_V: 75V; AEC Category: Q200; SizeAreaWB_mm2: 4.68
R155 R217 = CMP-0078662-1: RES, 18.0 k, 1%, 0.1 W, AEC-Q200 Grade 0, 0603; Manufacturer: Panasonic; Power_W: 100mW; TempCo: 100 ppm/C; Value_Code: 18k0; Value: 18.0k; Res_ohm: 18k; SizeX_mm: 1.6; SizeY_mm: 0.8; SizeZ_mm: 1; Value2: 0.1W; SizeArea_mm2: 1.28; AEC Qualified: Y; AEC Grade: 0; AEC Category: Q200
R171 R223 = CMP-0023000-5: RES, 2.00 k, 1%, 0.1 W, 0603; Manufacturer: Yageo; Power_W: 100mW; TempCo: 100 ppm/C; Value_Code: 2k00; Value: 2.00k; EIA_Code: E96; Res_ohm: 2k; SizeX_mm: 1.6; SizeY_mm: 0.8; SizeZ_mm: 1; Value2: 0.1W; SizeArea_mm2: 1.28; AEC Qualified: N; VDC_V: 75V; AEC Category: Q200; SizeAreaWB_mm2: 4.68
R172 R173 = CMP-0025874-4: RES, 0, 5%, 0.1 W, AEC-Q200 Grade 0, 0603; Manufacturer: Panasonic; Value: 0; Value_Code: 0000; Power_W: 100mW; Value2: 0.1W; VDC_V: 50V; TempCo: 600 ppm/C; SizeArea_mm2: 1.28; SizeX_mm: 1.6; SizeY_mm: 0.8; SizeZ_mm: 1; EIA_Code: E24; AEC Category: Q200; AEC Qualified: Y; SizeAreaWB_mm2: 4.68
R183 = CMP-0025946-3: RES, 1.0 k, 5%, 0.1 W, AEC-Q200 Grade 0, 0603; Manufacturer: Vishay-Dale; Power_W: 100mW; TempCo: 200 ppm/C; Value_Code: 1k00; U/M: EA; Value: 1.0k; EIA_Code: E24; Res_ohm: 1k; SizeX_mm: 1.6; SizeY_mm: 0.8; SizeZ_mm: 1; Value2: 0.1W; SizeArea_mm2: 1.28; AEC Qualified: Y; VDC_V: 75V; AEC Grade: 0; AEC Category: Q200
R185 R187 = CMP-0025698-4: RES, 100 k, 5%, 0.1 W, AEC-Q200 Grade 0, 0603; Manufacturer: Vishay-Dale; Power_W: 100mW; TempCo: 200 ppm/C; Value: 100k; EIA_Code: E24; SizeX_mm: 1.6; SizeY_mm: 0.8; SizeZ_mm: 1; Value2: 0.1W; SizeArea_mm2: 1.28; AEC Qualified: Y; VDC_V: 75V; AEC Category: Q200; AEC Grade: 0
R188 R191 = CMP-0023642-3: RES, 107 k, 0.1%, 0.1 W, 0603; Manufacturer: Yageo America; Power_W: 100mW; TempCo: 25 ppm/C; U/M: EA; Value: 107k; EIA_Code: E192; SizeX_mm: 1.6; SizeY_mm: 0.8; SizeZ_mm: 1; Value2: 0.1W; SizeArea_mm2: 1.28; VDC_V: 75V; AEC Category: Q200
R189 R192 = CMP-0023508-3: RES, 30.0 k, 0.1%, 0.1 W, 0603; Manufacturer: Susumu Co Ltd; Power_W: 100mW; TempCo: 25 ppm/C; Value_Code: 30k0; U/M: EA; Value: 30.0k; Res_ohm: 30k; SizeX_mm: 1.6; SizeY_mm: 0.8; SizeZ_mm: 1; Value2: 0.1W; SizeArea_mm2: 1.28; VDC_V: 75V; AEC Category: Q200
R196 R198 = CMP-0023798-3: RES, 16.2 k, 0.1%, 0.1 W, 0603; Manufacturer: Yageo America; Power_W: 100mW; TempCo: 25 ppm/C; Value_Code: 16k2; U/M: EA; Value: 16.2k; EIA_Code: E192; SizeX_mm: 1.6; SizeY_mm: 0.8; SizeZ_mm: 1; Value2: 0.1W; SizeArea_mm2: 1.28; VDC_V: 75V; AEC Category: Q200
R197 R199 = CMP-0024283-3: RES, 49.9 k, 0.1%, 0.1 W, 0603; Manufacturer: Yageo America; Power_W: 100mW; TempCo: 25 ppm/C; Value_Code: 49k9; U/M: EA; Value: 49.9k; EIA_Code: E192; SizeX_mm: 1.6; SizeY_mm: 0.8; SizeZ_mm: 1; Value2: 0.1W; SizeArea_mm2: 1.28; VDC_V: 75V; AEC Category: Q200
R200-R203 R214 R220 = CMP-0025700-4: RES, 100, 5%, 0.1 W, AEC-Q200 Grade 0, 0603; Manufacturer: Vishay-Dale; Power_W: 100mW; TempCo: 200 ppm/C; Value_Code: 100R; Value: 100; EIA_Code: E24; SizeX_mm: 1.6; SizeY_mm: 0.8; SizeZ_mm: 1; Value2: 0.1W; SizeArea_mm2: 1.28; AEC Qualified: Y; VDC_V: 75V; AEC Category: Q200; AEC Grade: 0
R209 R215 R216 R218 = CMP-0018648-3: RES, 2.0, 5%, 0.25 W, AEC-Q200 Grade 0, 1206; Manufacturer: Vishay-Dale; Power_W: 250mW; TempCo: 200 ppm/C; Value_Code: 2R00; Value: 2.0; EIA_Code: E24; Res_ohm: 2; SizeX_mm: 3.2; SizeY_mm: 1.6; SizeZ_mm: 1.35; Value2: 0.25W; SizeArea_mm2: 5.12; AEC Qualified: Y; VDC_V: 200V; AEC Category: Q200; AEC Grade: 0
RT1 = CMP-0084566-1: Thermistor, DEC0002A (X1SON-2); Alternate Manufacturer: Texas Instruments; Alternate PartNumber: TMP6131DECT; CompType: IC; AEC Category: Q200; SizeX_mm: 1; AEC Qualified: N; SizeZ_mm: 0.5; SizeArea_mm2: 0.6; SizeAreaWB_mm2: 3.2
U14 U24 = CMP-0034067-2: Automotive 1.5-W, 12-V VIN, 25-V VOUT, High-Density, > 5 kVRMS, Isolated DC/DC Module; Manufacturer: Texas Instruments; SizeZ_mm: 3.55mm; AEC Qualified: Yes; AEC Grade: Grade 1; Max Supply Voltage: 18V; Min Supply Voltage: 8V; Nominal Supply Current: 200-270mA; Number Of Outputs: 2; Output Type: AdjustableProgrammable; Output Voltage: 18-25V; Standoff Height: 0.1mm; Switching Frequency: 16MHz; TaMax_C: +125°C; TaMin_C: -40°C; TJmax_C: +150°C; AEC Category: Q200; CompType: IC
U26 = CMP-0066280-1: Quadruple Bus Buffer Gate with 3-State Outputs, PW0014A (TSSOP-14); Manufacturer: Texas Instruments; SizeArea_mm2: 32.0; SizeAreaWB_mm2: 58.8; SizeX_mm: 6.4; SizeY_mm: 5.0; SizeZ_mm: 1.2; CompType: IC; U/M: EA
U29 U30 = CMP-0080534-2: Single Channel Isolated Gate Driver for SiC/IGBT with Advanced Protection and High-CMTI, DW0016B (SOIC-16); Manufacturer: Texas Instruments; Alternate PartNumber: UCC21710QDWRQ1; SizeY_mm: 10.3; CompType: IC; AEC Qualified: Y; SizeArea_mm2: 107.12; SizeAreaWB_mm2: 152.52; SizeZ_mm: 2.65; SizeX_mm: 10.4; AEC Category: Q200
